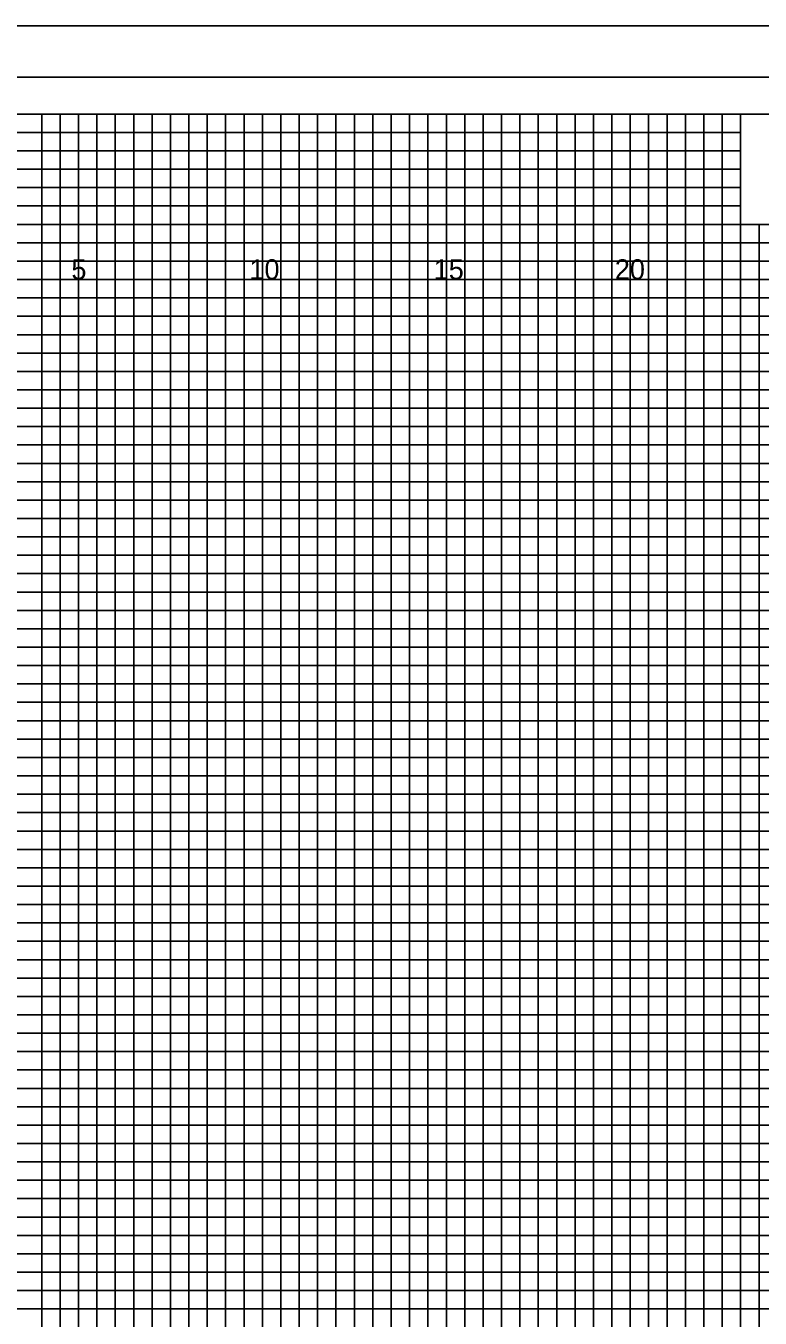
# Model space of a CAD drawing. Extents: x -4 to 103, y -2 to 138.
# Drawn here: x 54.82 to 74.78, y 103.08 to 138.22 of the extents above; entities that cross this region are included whole.
import ezdxf

# ---------------------------------------------------------------- set-up
doc = ezdxf.new("R2010")
doc.units = 0
for name, color, linetype in [('Exist XS Ground Line', 7, 'Continuous'), ('Old_Level_10', 7, 'Continuous'), ('Old_Level_16', 7, 'Continuous'), ('Old_Level_3', 7, 'Continuous'), ('Old_Level_5', 7, 'Continuous'), ('Old_Level_8', 7, 'Continuous'), ('Prop XS Elevation Labels', 7, 'Continuous'), ('Prop XS Finish Grade', 7, 'Continuous')]:
    doc.layers.add(name, color=color, linetype=linetype)

msp = doc.modelspace()

# ---------------------------------------------------------------- linework, layer by layer
at = {"layer": 'Exist XS Ground Line'}
msp.add_lwpolyline([(103, 136.825), (-2.8, 136.825), (-2.8, 69.825), (103, 69.825)], close=True, dxfattribs=at)
at = {"layer": 'Old_Level_10'}
for p, q in [((56.25, 70.825), (56.25, 135.825)), ((58.75, 70.825), (58.75, 135.825)), ((61.25, 70.825), (61.25, 135.825)), ((63.75, 70.825), (63.75, 135.825)), ((66.25, 70.825), (66.25, 135.825)), ((68.75, 70.825), (68.75, 135.825)), ((71.25, 70.825), (71.25, 135.825)), ((73.75, 70.825), (73.75, 135.825)), ((0, 133.325), (74.25, 133.325)), ((0, 130.825), (102.5, 130.825)), ((0, 128.325), (102.5, 128.325)), ((0, 125.825), (102.5, 125.825)), ((0, 123.325), (102.5, 123.325)), ((0, 120.825), (102.5, 120.825)), ((0, 118.325), (102.5, 118.325)), ((0, 115.825), (102.5, 115.825)), ((0, 113.325), (102.5, 113.325)), ((0, 110.825), (102.5, 110.825)), ((0, 108.325), (102.5, 108.325)), ((0, 105.825), (102.5, 105.825)), ((0, 103.325), (102.5, 103.325))]:
    msp.add_line(p, q, dxfattribs=at)
at = {"layer": 'Old_Level_3'}
msp.add_line((-3.5, 138.225), (103.4, 138.225), dxfattribs=at)
at = {"layer": 'Old_Level_5'}
msp.add_lwpolyline([(103.4, 138.225), (-3.5, 138.225), (-3.5, 68.4), (103.4, 68.4)], close=True, dxfattribs=at)
at = {"layer": 'Old_Level_8'}
for points in [[(56.25, 70.825), (56.25, 135.825), (58.75, 135.825), (58.75, 70.825)], [(61.25, 70.825), (61.25, 135.825), (63.75, 135.825), (63.75, 70.825)], [(66.25, 70.825), (66.25, 135.825), (68.75, 135.825), (68.75, 70.825)], [(71.25, 70.825), (71.25, 135.825), (73.75, 135.825), (73.75, 70.825)], [(0, 133.325), (74.25, 133.325)], [(0, 128.325), (102.5, 128.325), (102.5, 130.825), (0, 130.825)], [(0, 123.325), (102.5, 123.325), (102.5, 125.825), (0, 125.825)], [(0, 118.325), (102.5, 118.325), (102.5, 120.825), (0, 120.825)], [(0, 113.325), (102.5, 113.325), (102.5, 115.825), (0, 115.825)], [(0, 108.325), (102.5, 108.325), (102.5, 110.825), (0, 110.825)], [(0, 103.325), (102.5, 103.325), (102.5, 105.825), (0, 105.825)]]:
    msp.add_lwpolyline(points, dxfattribs=at)
at = {"layer": 'Prop XS Elevation Labels'}
for points in [[(102.5, 135.825), (0, 135.825), (0, 70.825), (102.5, 70.825)], [(83.75, 135.825), (74.25, 135.825), (74.25, 132.825), (83.75, 132.825)]]:
    msp.add_lwpolyline(points, close=True, dxfattribs=at)
at = {"layer": 'Prop XS Finish Grade'}
for points in [[(55.25, 70.825), (55.25, 135.825), (55.75, 135.825), (55.75, 70.825)], [(56.75, 70.825), (56.75, 135.825), (57.25, 135.825), (57.25, 70.825)], [(57.75, 70.825), (57.75, 135.825), (58.25, 135.825), (58.25, 70.825)], [(59.25, 70.825), (59.25, 135.825), (59.75, 135.825), (59.75, 70.825)], [(60.25, 70.825), (60.25, 135.825), (60.75, 135.825), (60.75, 70.825)], [(61.75, 70.825), (61.75, 135.825), (62.25, 135.825), (62.25, 70.825)], [(62.75, 70.825), (62.75, 135.825), (63.25, 135.825), (63.25, 70.825)], [(64.25, 70.825), (64.25, 135.825), (64.75, 135.825), (64.75, 70.825)], [(65.25, 70.825), (65.25, 135.825), (65.75, 135.825), (65.75, 70.825)], [(66.75, 70.825), (66.75, 135.825), (67.25, 135.825), (67.25, 70.825)], [(67.75, 70.825), (67.75, 135.825), (68.25, 135.825), (68.25, 70.825)], [(69.25, 70.825), (69.25, 135.825)], [(69.25, 135.825), (69.75, 135.825), (69.75, 70.825)], [(70.25, 70.825), (70.25, 135.825), (70.75, 135.825), (70.75, 70.825)], [(71.75, 70.825), (71.75, 135.825), (72.25, 135.825), (72.25, 70.825)], [(72.75, 70.825), (72.75, 135.825), (73.25, 135.825), (73.25, 70.825)], [(0, 132.825), (0, 133.825), (74.25, 133.825), (74.25, 134.325), (0, 134.325), (0, 134.825), (74.25, 134.825), (74.25, 135.325), (0, 135.325)], [(0, 132.325), (102.5, 132.325), (102.5, 132.825), (0, 132.825)], [(74.25, 70.825), (74.25, 132.825), (74.75, 132.825), (74.75, 70.825)], [(0, 131.325), (102.5, 131.325), (102.5, 131.825), (0, 131.825)], [(0, 129.825), (102.5, 129.825), (102.5, 130.325), (0, 130.325)], [(0, 128.825), (102.5, 128.825), (102.5, 129.325), (0, 129.325)], [(0, 127.325), (102.5, 127.325), (102.5, 127.825), (0, 127.825)], [(0, 126.325), (102.5, 126.325), (102.5, 126.825), (0, 126.825)], [(0, 124.825), (102.5, 124.825), (102.5, 125.325), (0, 125.325)], [(0, 123.825), (102.5, 123.825), (102.5, 124.325), (0, 124.325)], [(0, 122.325), (102.5, 122.325), (102.5, 122.825), (0, 122.825)], [(0, 121.325), (102.5, 121.325), (102.5, 121.825), (0, 121.825)], [(0, 119.825), (102.5, 119.825), (102.5, 120.325), (0, 120.325)], [(0, 118.825), (102.5, 118.825), (102.5, 119.325), (0, 119.325)], [(0, 117.325), (102.5, 117.325), (102.5, 117.825), (0, 117.825)], [(0, 116.325), (102.5, 116.325), (102.5, 116.825), (0, 116.825)], [(0, 114.825), (102.5, 114.825), (102.5, 115.325), (0, 115.325)], [(0, 113.825), (102.5, 113.825), (102.5, 114.325), (0, 114.325)], [(0, 112.325), (102.5, 112.325), (102.5, 112.825), (0, 112.825)], [(0, 111.325), (102.5, 111.325), (102.5, 111.825), (0, 111.825)], [(0, 109.825), (102.5, 109.825), (102.5, 110.325), (0, 110.325)], [(0, 108.825), (102.5, 108.825), (102.5, 109.325), (0, 109.325)], [(0, 107.325), (102.5, 107.325), (102.5, 107.825), (0, 107.825)], [(0, 106.325), (102.5, 106.325), (102.5, 106.825), (0, 106.825)], [(0, 104.825), (102.5, 104.825), (102.5, 105.325), (0, 105.325)], [(0, 103.825), (102.5, 103.825), (102.5, 104.325), (0, 104.325)]]:
    msp.add_lwpolyline(points, dxfattribs=at)

# ---------------------------------------------------------------- texts
at = {"layer": 'Old_Level_16'}
for s, p in [('5', (56.057, 131.325)), ('10', (60.897, 131.325)), ('15', (65.906, 131.325)), ('20', (70.831, 131.325))]:
    msp.add_text(s, height=0.55, dxfattribs=at).set_placement(p)

doc.saveas('drawing.dxf')
